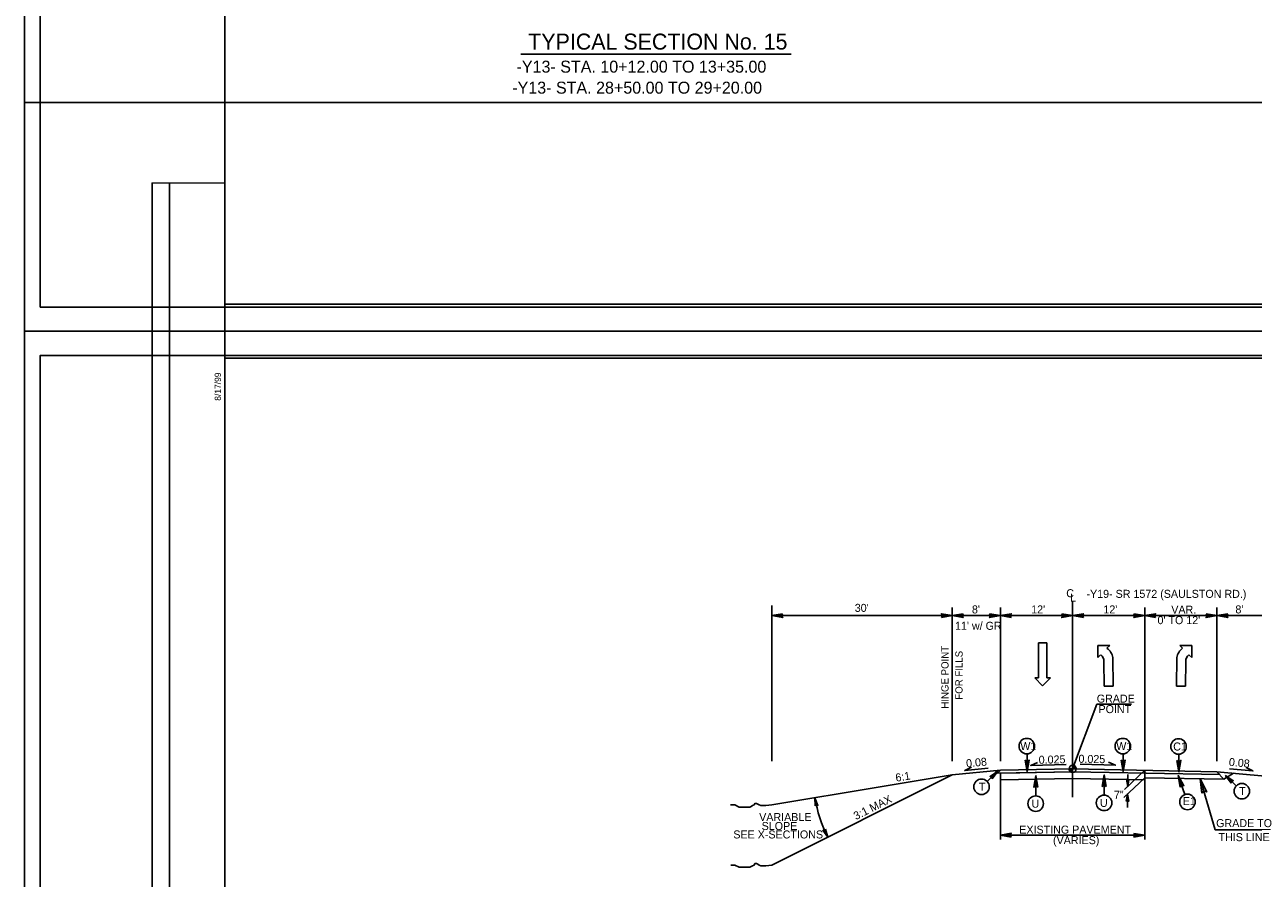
# Model space of a CAD drawing. Extents: x 2320980 to 2456309, y 595047 to 606177.
# Drawn here: x 2455708.8 to 2455913.1, y 595774.7 to 595916.5 of the extents above; entities that cross this region are included whole.
import ezdxf

# ---------------------------------------------------------------- set-up
doc = ezdxf.new("R2010")
doc.units = 0
for name, color, linetype in [('Old_Level_1', 7, 'Continuous'), ('Old_Level_11', 7, 'Continuous'), ('Old_Level_2', 7, 'Continuous'), ('Old_Level_20', 7, 'Continuous'), ('Old_Level_21', 7, 'Continuous'), ('Old_Level_3', 7, 'Continuous'), ('Prop Dimension', 7, 'Continuous'), ('Prop Dimension Text', 7, 'Continuous'), ('Prop Lane Arrow CELL', 7, 'Continuous'), ('Prop Terminator CELL', 7, 'Continuous'), ('Sheet Block Revision CELL', 7, 'Continuous'), ('Sheet Cutting Line CELL', 7, 'Continuous'), ('Sheet Plan CELL', 7, 'Continuous'), ('Sheet Plot Border Inside CELL', 7, 'Continuous'), ('Sheet Plot Border Outside CELL', 7, 'Continuous'), ('Typical Grade Point Symbol CELL', 7, 'Continuous'), ('Typical Hinge Slope Arterial CELL', 7, 'Continuous'), ('Typical ID Circle CELL', 7, 'Continuous'), ('Typical Pavement Slope CELL', 7, 'Continuous'), ('Typical Pavement Slope Information CELL', 7, 'Continuous'), ('Typical Terminator CELL', 7, 'Continuous')]:
    doc.layers.add(name, color=color, linetype=linetype)

msp = doc.modelspace()

# ---------------------------------------------------------------- linework, layer by layer
at = {"layer": 'Old_Level_1'}
for p, q in [((2455883.04, 595792.88), (2455887.04, 595803.61)), ((2455887.04, 595803.61), (2455892.8, 595803.61)), ((2455871.04, 595792.64), (2455863.04, 595791.89)), ((2455870.55, 595792.15), (2455870.18, 595792.56)), ((2455870.55, 595792.15), (2455871.04, 595792.64)), ((2455874.29, 595792.23), (2455870.55, 595792.15)), ((2455883.04, 595792.4), (2455871.04, 595792.16)), ((2455871.04, 595791.06), (2455871.04, 595792.16)), ((2455883.04, 595792.4), (2455907.49, 595791.92)), ((2455895.04, 595791.41), (2455895.04, 595792.64)), ((2455895.04, 595791.41), (2455908.19, 595791.15)), ((2455895.04, 595791.06), (2455895.04, 595791.41)), ((2455907.04, 595792.4), (2455915.04, 595791.66)), ((2455908.19, 595791.15), (2455909.8, 595792.16)), ((2455883.04, 595791.3), (2455871.04, 595791.06)), ((2455883.04, 595791.3), (2455895.04, 595791.06))]:
    msp.add_line(p, q, dxfattribs=at)
at = {"layer": 'Old_Level_11'}
msp.add_lwpolyline([(2455904.53, 595788.82), (2455904.26, 595791.23), (2455905.34, 595789.04), (2455904.84, 595789.21)], close=True, dxfattribs=at)
at = {"layer": 'Old_Level_21'}
for p, q in [((2455833.04, 595794.17), (2455833.04, 595820.03)), ((2455863.04, 595818.34), (2455833.04, 595818.34)), ((2455863.04, 595794.17), (2455863.04, 595819.67)), ((2455863.04, 595818.34), (2455871.04, 595818.34)), ((2455871.04, 595794.17), (2455871.04, 595819.67)), ((2455883.04, 595818.34), (2455871.04, 595818.34)), ((2455895.04, 595818.34), (2455883.04, 595818.34)), ((2455895.04, 595794.17), (2455895.04, 595819.67)), ((2455907.04, 595818.34), (2455895.04, 595818.34)), ((2455907.04, 595794.17), (2455907.04, 595819.67)), ((2455915.04, 595818.34), (2455907.04, 595818.34)), ((2455871.04, 595781.17), (2455871.04, 595791.06)), ((2455895.04, 595781.17), (2455895.04, 595791.06)), ((2455906.73, 595782.74), (2455904.26, 595791.23)), ((2455895.04, 595781.85), (2455871.04, 595781.85)), ((2455915.93, 595782.74), (2455906.73, 595782.74))]:
    msp.add_line(p, q, dxfattribs=at)
at = {"layer": 'Old_Level_3'}
msp.add_line((2455791.32, 595911.63), (2455836.24, 595911.63), dxfattribs=at)
at = {"layer": 'Prop Dimension'}
for p, q in [((2455895.04, 595791.41), (2455891.53, 595788.11)), ((2455895.04, 595791.41), (2455891.53, 595788.11)), ((2455895.07, 595792.65), (2455891.69, 595789.46)), ((2455895.07, 595792.65), (2455891.69, 595789.46)), ((2455892.19, 595791.93), (2455892.19, 595789.93)), ((2455892.19, 595791.93), (2455892.19, 595789.93)), ((2455892.16, 595788.7), (2455892.16, 595786.45)), ((2455892.16, 595788.7), (2455892.16, 595786.45))]:
    msp.add_line(p, q, dxfattribs=at)
at = {"layer": 'Prop Dimension Text'}
for p, q in [((2455883.04, 595799.38), (2455883.04, 595820.68)), ((2455883.04, 595788.19), (2455883.04, 595799.38)), ((2455868.83, 595790.79), (2455870.59, 595792.47)), ((2455910.23, 595790.07), (2455908.47, 595791.75))]:
    msp.add_line(p, q, dxfattribs=at)
for points in [[(2455881.94, 595793.62), (2455876.08, 595793.46), (2455877.22, 595793.94)], [(2455884.28, 595793.64), (2455890.14, 595793.48), (2455889, 595793.97)], [(2455869, 595792.98), (2455865.1, 595792.6), (2455866.2, 595793.17)], [(2455909.11, 595792.9), (2455913, 595792.53), (2455911.9, 595793.1)]]:
    msp.add_lwpolyline(points, dxfattribs=at)
for centre in [(2455875.42, 595796.66), (2455891.38, 595796.66), (2455900.65, 595796.6), (2455867.9, 595789.9), (2455911.17, 595789.17), (2455876.9, 595787.1), (2455888.27, 595787.23), (2455902.13, 595787.39)]:
    msp.add_circle(centre, 1.29, dxfattribs=at)
at = {"layer": 'Prop Lane Arrow CELL'}
for p, q in [((2455877.39, 595813.82), (2455877.39, 595808)), ((2455878.76, 595813.82), (2455877.39, 595813.82)), ((2455878.76, 595808), (2455878.76, 595813.82)), ((2455889.21, 595813.39), (2455887.23, 595813.38)), ((2455887.23, 595813.38), (2455887.24, 595811.36)), ((2455887.24, 595811.36), (2455887.7, 595811.83)), ((2455888.74, 595812.91), (2455889.21, 595813.39)), ((2455901.33, 595812.91), (2455900.87, 595813.39)), ((2455900.87, 595813.39), (2455902.85, 595813.38)), ((2455902.84, 595811.36), (2455902.38, 595811.83)), ((2455902.85, 595813.38), (2455902.84, 595811.36)), ((2455888.23, 595810.72), (2455888.3, 595806.6)), ((2455889.78, 595806.62), (2455889.71, 595811.37)), ((2455900.3, 595806.62), (2455900.37, 595811.37)), ((2455901.84, 595810.72), (2455901.78, 595806.6)), ((2455877.39, 595808), (2455876.76, 595808)), ((2455876.76, 595808), (2455878.05, 595806.69)), ((2455878.05, 595806.69), (2455879.38, 595808)), ((2455879.38, 595808), (2455878.76, 595808)), ((2455888.3, 595806.6), (2455889.78, 595806.62)), ((2455901.78, 595806.6), (2455900.3, 595806.62))]:
    msp.add_line(p, q, dxfattribs=at)
for centre, radius, start, end in [((2455886.77, 595810.7), 1.47, 0.8411, 50.4993), ((2455887.39, 595810.98), 2.36, 9.5172, 54.8289), ((2455902.69, 595810.98), 2.36, 125.1711, 170.4828), ((2455903.31, 595810.7), 1.47, 129.5007, 179.1589)]:
    msp.add_arc(centre, radius, start, end, dxfattribs=at)
at = {"layer": 'Prop Terminator CELL'}
for points in [[(2455892.4, 595791.13), (2455892.19, 595789.93), (2455891.98, 595791.14), (2455892.19, 595790.98)], [(2455892.4, 595791.13), (2455892.19, 595789.93), (2455891.98, 595791.14), (2455892.19, 595790.98)], [(2455891.96, 595787.5), (2455892.16, 595788.7), (2455892.37, 595787.5), (2455892.16, 595787.65)], [(2455891.96, 595787.5), (2455892.16, 595788.7), (2455892.37, 595787.5), (2455892.16, 595787.65)]]:
    msp.add_lwpolyline(points, close=True, dxfattribs=at)
at = {"layer": 'Sheet Block Revision CELL'}
msp.add_line((2455732.91, 595732.08), (2455732.91, 595890.2), dxfattribs=at)
msp.add_lwpolyline([(2455730, 595732.07), (2455730, 595890.2), (2455742.11, 595890.21), (2455742.11, 595732.08)], close=True, dxfattribs=at)
at = {"layer": 'Sheet Cutting Line CELL'}
for p, q in [((2456045.51, 595903.57), (2455708.81, 595903.57)), ((2455708.81, 595903.57), (2455708.81, 595684.57))]:
    msp.add_line(p, q, dxfattribs=at)
at = {"layer": 'Sheet Plan CELL'}
msp.add_line((2455742.1, 595861.08), (2455742.1, 595861.08), dxfattribs=at)
for points in [[(2456042.11, 596080.08), (2455742.1, 596080.08), (2455742.1, 595870.08), (2456042.11, 595870.08)], [(2455742.1, 595870.08), (2455742.1, 596080.07), (2456002.1, 596080.08), (2456002.1, 596050.07), (2456042.11, 596050.06), (2456042.11, 595870.08)], [(2456042.11, 595861.08), (2455742.1, 595861.08), (2455742.1, 595651.08), (2456042.11, 595651.08)], [(2455742.1, 595651.08), (2455742.1, 595861.07), (2456002.1, 595861.08), (2456002.1, 595831.07), (2456042.11, 595831.06), (2456042.11, 595651.08)]]:
    msp.add_lwpolyline(points, close=True, dxfattribs=at)
at = {"layer": 'Sheet Plot Border Inside CELL'}
for points in [[(2455711.41, 595869.57), (2456044.6, 595869.58), (2456044.61, 596080.57), (2455711.41, 596080.57)], [(2455711.41, 595650.57), (2456044.6, 595650.58), (2456044.61, 595861.57), (2455711.41, 595861.57)]]:
    msp.add_lwpolyline(points, close=True, dxfattribs=at)
at = {"layer": 'Sheet Plot Border Outside CELL'}
for points in [[(2455708.81, 595865.57), (2456045.51, 595865.57), (2456045.51, 596084.57), (2455708.81, 596084.57)], [(2455708.81, 595646.57), (2456045.51, 595646.57), (2456045.51, 595865.57), (2455708.81, 595865.57)]]:
    msp.add_lwpolyline(points, close=True, dxfattribs=at)
at = {"layer": 'Typical Grade Point Symbol CELL'}
for p, q in [((2455883.04, 595792.88), (2455883.04, 595793.48)), ((2455882.44, 595792.88), (2455883.04, 595792.88)), ((2455883.63, 595792.88), (2455883.04, 595792.88)), ((2455883.04, 595792.29), (2455883.04, 595792.88)), ((2455883.04, 595792.88), (2455883.04, 595792.29))]:
    msp.add_line(p, q, dxfattribs=at)
for points in [[(2455883.04, 595793.48), (2455883.04, 595793.48), (2455883.04, 595792.88)], [(2455883.05, 595793.48), (2455883.05, 595792.88)], [(2455883.07, 595793.48), (2455883.07, 595792.88)], [(2455883.08, 595793.48), (2455883.08, 595792.88)], [(2455883.09, 595793.48), (2455883.09, 595792.88)], [(2455883.1, 595793.48), (2455883.1, 595792.88)], [(2455883.11, 595793.47), (2455883.11, 595792.88)], [(2455883.13, 595793.47), (2455883.13, 595792.88)], [(2455883.14, 595793.47), (2455883.14, 595792.88)], [(2455883.15, 595793.47), (2455883.15, 595792.88)], [(2455883.16, 595793.47), (2455883.16, 595792.88)], [(2455883.17, 595793.46), (2455883.17, 595792.88)], [(2455883.19, 595793.46), (2455883.19, 595792.88)], [(2455883.2, 595793.46), (2455883.2, 595792.88)], [(2455883.21, 595793.45), (2455883.21, 595792.88)], [(2455883.22, 595793.45), (2455883.22, 595792.88)], [(2455883.23, 595793.45), (2455883.23, 595792.88)], [(2455883.25, 595793.44), (2455883.25, 595792.88)], [(2455883.26, 595793.44), (2455883.26, 595792.88)], [(2455883.27, 595793.43), (2455883.27, 595792.88)], [(2455883.28, 595793.43), (2455883.28, 595792.88)], [(2455882.44, 595792.88), (2455882.44, 595792.82)], [(2455882.46, 595792.88), (2455882.46, 595792.75)], [(2455882.47, 595792.88), (2455882.47, 595792.71)], [(2455882.48, 595792.88), (2455882.48, 595792.67)], [(2455882.49, 595792.88), (2455882.49, 595792.64)], [(2455882.5, 595792.88), (2455882.5, 595792.62)], [(2455882.52, 595792.88), (2455882.52, 595792.6)], [(2455882.53, 595792.88), (2455882.53, 595792.57)], [(2455882.54, 595792.88), (2455882.54, 595792.56)], [(2455882.55, 595792.88), (2455882.55, 595792.54)], [(2455882.56, 595792.88), (2455882.56, 595792.52)], [(2455882.58, 595792.88), (2455882.58, 595792.51)], [(2455882.59, 595792.88), (2455882.59, 595792.49)], [(2455882.6, 595792.88), (2455882.6, 595792.48)], [(2455882.61, 595792.88), (2455882.61, 595792.47)], [(2455882.62, 595792.88), (2455882.62, 595792.46)], [(2455882.64, 595792.88), (2455882.64, 595792.44)], [(2455882.65, 595792.88), (2455882.65, 595792.43)], [(2455882.66, 595792.88), (2455882.66, 595792.42)], [(2455882.67, 595792.88), (2455882.67, 595792.41)], [(2455882.68, 595792.88), (2455882.68, 595792.41)], [(2455882.69, 595792.88), (2455882.69, 595792.4)], [(2455882.71, 595792.88), (2455882.71, 595792.39)], [(2455882.72, 595792.88), (2455882.72, 595792.38)], [(2455882.73, 595792.88), (2455882.73, 595792.37)], [(2455882.74, 595792.88), (2455882.74, 595792.37)], [(2455882.75, 595792.88), (2455882.75, 595792.36)], [(2455882.77, 595792.88), (2455882.77, 595792.35)], [(2455882.78, 595792.88), (2455882.78, 595792.35)], [(2455882.79, 595792.88), (2455882.79, 595792.34)], [(2455882.8, 595792.88), (2455882.8, 595792.34)], [(2455882.81, 595792.88), (2455882.81, 595792.33)], [(2455882.83, 595792.88), (2455882.83, 595792.33)], [(2455882.84, 595792.88), (2455882.84, 595792.32)], [(2455882.85, 595792.88), (2455882.85, 595792.32)], [(2455882.86, 595792.88), (2455882.86, 595792.32)], [(2455882.87, 595792.88), (2455882.87, 595792.31)], [(2455882.89, 595792.88), (2455882.89, 595792.31)], [(2455882.9, 595792.88), (2455882.9, 595792.31)], [(2455882.91, 595792.88), (2455882.91, 595792.3)], [(2455882.92, 595792.88), (2455882.92, 595792.3)], [(2455882.93, 595792.88), (2455882.93, 595792.3)], [(2455882.94, 595792.88), (2455882.94, 595792.3)], [(2455882.96, 595792.88), (2455882.96, 595792.29)], [(2455882.97, 595792.88), (2455882.97, 595792.29)], [(2455882.98, 595792.88), (2455882.98, 595792.29)], [(2455882.99, 595792.88), (2455882.99, 595792.29)], [(2455883, 595792.88), (2455883, 595792.29)], [(2455883.02, 595792.88), (2455883.02, 595792.29)], [(2455883.03, 595792.88), (2455883.03, 595792.29), (2455883.03, 595792.29)], [(2455883.29, 595793.42), (2455883.29, 595792.88)], [(2455883.3, 595793.42), (2455883.3, 595792.88)], [(2455883.32, 595793.41), (2455883.32, 595792.88)], [(2455883.33, 595793.4), (2455883.33, 595792.88)], [(2455883.34, 595793.4), (2455883.34, 595792.88)], [(2455883.35, 595793.39), (2455883.35, 595792.88)], [(2455883.36, 595793.38), (2455883.36, 595792.88)], [(2455883.38, 595793.37), (2455883.38, 595792.88)], [(2455883.39, 595793.36), (2455883.39, 595792.88)], [(2455883.4, 595793.36), (2455883.4, 595792.88)], [(2455883.41, 595793.35), (2455883.41, 595792.88)], [(2455883.42, 595793.34), (2455883.42, 595792.88)], [(2455883.44, 595793.33), (2455883.44, 595792.88)], [(2455883.45, 595793.32), (2455883.45, 595792.88)], [(2455883.46, 595793.3), (2455883.46, 595792.88)], [(2455883.47, 595793.29), (2455883.47, 595792.88)], [(2455883.48, 595793.28), (2455883.48, 595792.88)], [(2455883.5, 595793.26), (2455883.5, 595792.88)], [(2455883.51, 595793.25), (2455883.51, 595792.88)], [(2455883.52, 595793.23), (2455883.52, 595792.88)], [(2455883.53, 595793.22), (2455883.53, 595792.88)], [(2455883.54, 595793.2), (2455883.54, 595792.88)], [(2455883.55, 595793.18), (2455883.55, 595792.88)], [(2455883.57, 595793.16), (2455883.57, 595792.88)], [(2455883.58, 595793.13), (2455883.58, 595792.88)], [(2455883.59, 595793.1), (2455883.59, 595792.88)], [(2455883.6, 595793.07), (2455883.6, 595792.88)], [(2455883.61, 595793.03), (2455883.61, 595792.88)], [(2455883.63, 595792.97), (2455883.63, 595792.88)]]:
    msp.add_lwpolyline(points, dxfattribs=at)
msp.add_circle((2455883.04, 595792.88), 0.595, dxfattribs=at)
for start, end in [(359.9905, 89.9905), (179.9905, 269.9905)]:
    msp.add_arc((2455883.04, 595792.88), 0.595, start, end, dxfattribs=at)
at = {"layer": 'Typical Hinge Slope Arterial CELL'}
for p, q in [((2455833.04, 595776.9), (2455863.04, 595791.89)), ((2455851.04, 595789.89), (2455863.04, 595791.89)), ((2455833.04, 595786.89), (2455851.04, 595789.89))]:
    msp.add_line(p, q, dxfattribs=at)
for points in [[(2455833.04, 595786.89), (2455832.06, 595786.77), (2455831.81, 595786.77), (2455831.44, 595786.77), (2455831.2, 595786.77), (2455830.95, 595786.89), (2455830.7, 595787.02), (2455830.46, 595787.14), (2455830.21, 595787.14), (2455830.09, 595786.89), (2455829.84, 595786.77), (2455829.59, 595786.65), (2455829.35, 595786.53), (2455829.1, 595786.53), (2455828.85, 595786.53), (2455828.61, 595786.53), (2455828.36, 595786.53), (2455828.12, 595786.53), (2455827.87, 595786.53), (2455827.62, 595786.53), (2455827.38, 595786.65), (2455827.13, 595786.77), (2455826.88, 595786.89), (2455826.51, 595786.89), (2455826.27, 595786.89), (2455826.15, 595786.89)], [(2455833.04, 595776.9), (2455832.06, 595776.77), (2455831.81, 595776.77), (2455831.44, 595776.77), (2455831.2, 595776.77), (2455830.95, 595776.9), (2455830.7, 595777.02), (2455830.46, 595777.14), (2455830.21, 595777.14), (2455830.09, 595776.9), (2455829.84, 595776.77), (2455829.59, 595776.65), (2455829.35, 595776.53), (2455829.1, 595776.53), (2455828.85, 595776.53), (2455828.61, 595776.53), (2455828.36, 595776.53), (2455828.12, 595776.53), (2455827.87, 595776.53), (2455827.62, 595776.53), (2455827.38, 595776.65), (2455827.13, 595776.77), (2455826.88, 595776.9), (2455826.51, 595776.9), (2455826.27, 595776.9), (2455826.22, 595776.9)]]:
    msp.add_lwpolyline(points, dxfattribs=at)
msp.add_arc((2455863.04, 595791.89), 23.16, 189.4624, 206.565, dxfattribs=at)
at = {"layer": 'Typical ID Circle CELL'}
for p, q in [((2455875.47, 595795.38), (2455875.47, 595792.44)), ((2455891.43, 595795.38), (2455891.43, 595792.44)), ((2455900.7, 595795.32), (2455900.7, 595792.38)), ((2455876.93, 595788.4), (2455876.93, 595791.73)), ((2455888.3, 595788.52), (2455888.3, 595791.86)), ((2455901.68, 595788.61), (2455900.59, 595791.76))]:
    msp.add_line(p, q, dxfattribs=at)
at = {"layer": 'Typical Pavement Slope CELL'}
for p, q in [((2455871.04, 595792.64), (2455870.55, 595792.15)), ((2455870.55, 595792.15), (2455883.04, 595792.4)), ((2455883.04, 595792.88), (2455871.04, 595792.64)), ((2455883.04, 595792.88), (2455871.04, 595792.64)), ((2455883.04, 595792.88), (2455907.04, 595792.4)), ((2455883.04, 595792.4), (2455883.04, 595792.88)), ((2455907.04, 595792.4), (2455883.04, 595792.88)), ((2455883.04, 595792.88), (2455883.04, 595792.4)), ((2455883.04, 595792.4), (2455907.49, 595791.92)), ((2455895.04, 595791.41), (2455908.19, 595791.15)), ((2455907.49, 595791.92), (2455907.04, 595792.4)), ((2455908.19, 595791.15), (2455907.04, 595792.4))]:
    msp.add_line(p, q, dxfattribs=at)
at = {"layer": 'Typical Terminator CELL'}
for points in [[(2455834.83, 595818.65), (2455833.04, 595818.34), (2455834.84, 595818.02), (2455834.61, 595818.34)], [(2455861.24, 595818.03), (2455863.04, 595818.34), (2455861.23, 595818.66), (2455861.46, 595818.34)], [(2455864.83, 595818.65), (2455863.04, 595818.34), (2455864.84, 595818.02), (2455864.61, 595818.34)], [(2455869.24, 595818.65), (2455871.04, 595818.34), (2455869.23, 595818.02), (2455869.46, 595818.34)], [(2455872.83, 595818.03), (2455871.04, 595818.34), (2455872.84, 595818.66), (2455872.61, 595818.34)], [(2455881.24, 595818.65), (2455883.04, 595818.34), (2455881.23, 595818.02), (2455881.46, 595818.34)], [(2455884.83, 595818.03), (2455883.04, 595818.34), (2455884.84, 595818.66), (2455884.61, 595818.34)], [(2455893.24, 595818.65), (2455895.04, 595818.34), (2455893.23, 595818.02), (2455893.46, 595818.34)], [(2455896.83, 595818.03), (2455895.04, 595818.34), (2455896.84, 595818.66), (2455896.61, 595818.34)], [(2455905.24, 595818.65), (2455907.04, 595818.34), (2455905.23, 595818.02), (2455905.46, 595818.34)], [(2455908.83, 595818.65), (2455907.04, 595818.34), (2455908.84, 595818.02), (2455908.61, 595818.34)], [(2455875.15, 595794.34), (2455875.47, 595792.44), (2455875.81, 595794.35), (2455875.47, 595794.11)], [(2455891.1, 595794.34), (2455891.43, 595792.44), (2455891.76, 595794.35), (2455891.43, 595794.11)], [(2455900.37, 595794.28), (2455900.7, 595792.38), (2455901.04, 595794.29), (2455900.7, 595794.05)], [(2455869.69, 595791.25), (2455870.59, 595792.47), (2455869.32, 595791.62), (2455869.64, 595791.56)], [(2455877.26, 595789.84), (2455876.93, 595791.73), (2455876.59, 595789.83), (2455876.93, 595790.07)], [(2455888.63, 595789.97), (2455888.3, 595791.86), (2455887.96, 595789.96), (2455888.3, 595790.2)], [(2455900.9, 595789.86), (2455900.59, 595791.76), (2455901.53, 595790.07), (2455901.14, 595790.19)], [(2455909.38, 595790.53), (2455908.47, 595791.75), (2455909.74, 595790.9), (2455909.42, 595790.84)], [(2455840.23, 595786.72), (2455840.2, 595788.09), (2455840.69, 595786.8), (2455840.42, 595786.92)], [(2455841.97, 595782.86), (2455842.33, 595781.54), (2455841.53, 595782.67), (2455841.83, 595782.61)], [(2455872.83, 595781.55), (2455871.04, 595781.85), (2455872.84, 595782.17), (2455872.61, 595781.85)], [(2455893.24, 595782.16), (2455895.04, 595781.85), (2455893.23, 595781.54), (2455893.46, 595781.85)]]:
    msp.add_lwpolyline(points, close=True, dxfattribs=at)

# ---------------------------------------------------------------- texts
at = {"layer": 'Old_Level_1'}
for s, p in [('GRADE', (2455887.05, 595803.88)), ('POINT', (2455887.34, 595802.14))]:
    msp.add_text(s, height=1.33, dxfattribs=at).set_placement(p)
at = {"layer": 'Old_Level_2'}
for s, height, p in [('TYPICAL SECTION No. 15', 2.66, (2455792.54, 595912.36)), ('-Y13- STA. 10+12.00 TO 13+35.00', 1.995, (2455790.59, 595908.53)), ('-Y13- STA. 28+50.00 TO 29+20.00', 1.995, (2455789.88, 595905.04))]:
    msp.add_text(s, height=height, dxfattribs=at).set_placement(p)
at = {"layer": 'Old_Level_20'}
for s, p in [('W1', (2455874.34, 595795.99)), ('W1', (2455890.29, 595795.99)), ('C1', (2455899.76, 595795.93)), ('T', (2455867.46, 595789.23)), ('T', (2455910.73, 595788.51)), ('U', (2455876.21, 595786.43)), ('U', (2455887.58, 595786.56)), ('E1', (2455901.34, 595786.86))]:
    msp.add_text(s, height=1.33, dxfattribs=at).set_placement(p)
at = {"layer": 'Old_Level_21'}
for s, rotation, p in [('C', 0.0002, (2455881.98, 595821.39)), ('L', 0.0002, (2455882.64, 595820.68)), ('0.08', 5.3417, (2455865.39, 595793.12)), ('0.025', 1.1456, (2455877.41, 595793.72)), ('0.025', 358.8544, (2455884, 595793.9)), ('0.08', 354.6583, (2455908.97, 595793.39))]:
    msp.add_text(s, height=1.33, rotation=rotation, dxfattribs=at).set_placement(p)
for s, p in [('-Y19- SR 1572 (SAULSTON RD.)', (2455885.34, 595821.29)), ("30'", (2455846.82, 595818.96)), ("8'", (2455866.3, 595818.7)), ("12'", (2455876.15, 595818.7)), ("12'", (2455888.15, 595818.7)), ('VAR. ', (2455899.44, 595818.66)), ("8'", (2455910.1, 595818.7)), ("0' TO 12'", (2455897.15, 595816.92)), ("11' w/ GR", (2455863.49, 595815.98)), ('EXISTING PAVEMENT', (2455874.17, 595782.12)), ('GRADE TO', (2455906.9, 595783.2)), ('(VARIES)', (2455879.78, 595780.37)), ('THIS LINE', (2455907.29, 595780.87))]:
    msp.add_text(s, height=1.33, dxfattribs=at).set_placement(p)
at = {"layer": 'Prop Dimension Text'}
for s, p in [('HINGE POINT', (2455862.41, 595802.88)), ('FOR FILLS', (2455864.74, 595804.37))]:
    msp.add_text(s, height=1.2, rotation=90, dxfattribs=at).set_placement(p)
at = {"layer": 'Sheet Plan CELL'}
msp.add_text('8/17/99', height=1.05, rotation=90, dxfattribs=at).set_placement((2455741.46, 595854.03))
at = {"layer": 'Typical Hinge Slope Arterial CELL'}
for s, rotation, p in [('6:1', 9.4623, (2455853.7, 595790.73)), ('3:1 MAX', 26.5651, (2455847.02, 595784.36))]:
    msp.add_text(s, height=1.33, rotation=rotation, dxfattribs=at).set_placement(p)
for s, p in [('VARIABLE ', (2455830.93, 595784.21)), ('SLOPE', (2455831.34, 595782.72)), ('SEE X-SECTIONS', (2455826.63, 595781.32))]:
    msp.add_text(s, height=1.33, dxfattribs=at).set_placement(p)
at = {"layer": 'Typical Pavement Slope Information CELL'}
msp.add_text('7"', height=1.33, dxfattribs=at).set_placement((2455889.9, 595787.9))

doc.saveas('drawing.dxf')
